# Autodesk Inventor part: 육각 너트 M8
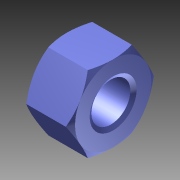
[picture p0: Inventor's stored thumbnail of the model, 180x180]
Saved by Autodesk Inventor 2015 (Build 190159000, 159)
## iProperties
Created: 2024-12
Part Number: 육각 너트 M8
Material: 일반
Document SubType Name: Modeling
Designer: 10401
Density: 1 g/cm^3
Appearance: 기본값
Author: 10401
Author: jhkim
Description: 6각 너트 및 6각 가는 너트
Creation Date: 2024-11-28
Sending System: Autodesk Inventor 2025
Preprocessor: ST-DEVELOPER v20
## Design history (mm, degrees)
node "육각 너트 M81"
body "Solid1"
node "기준1"
